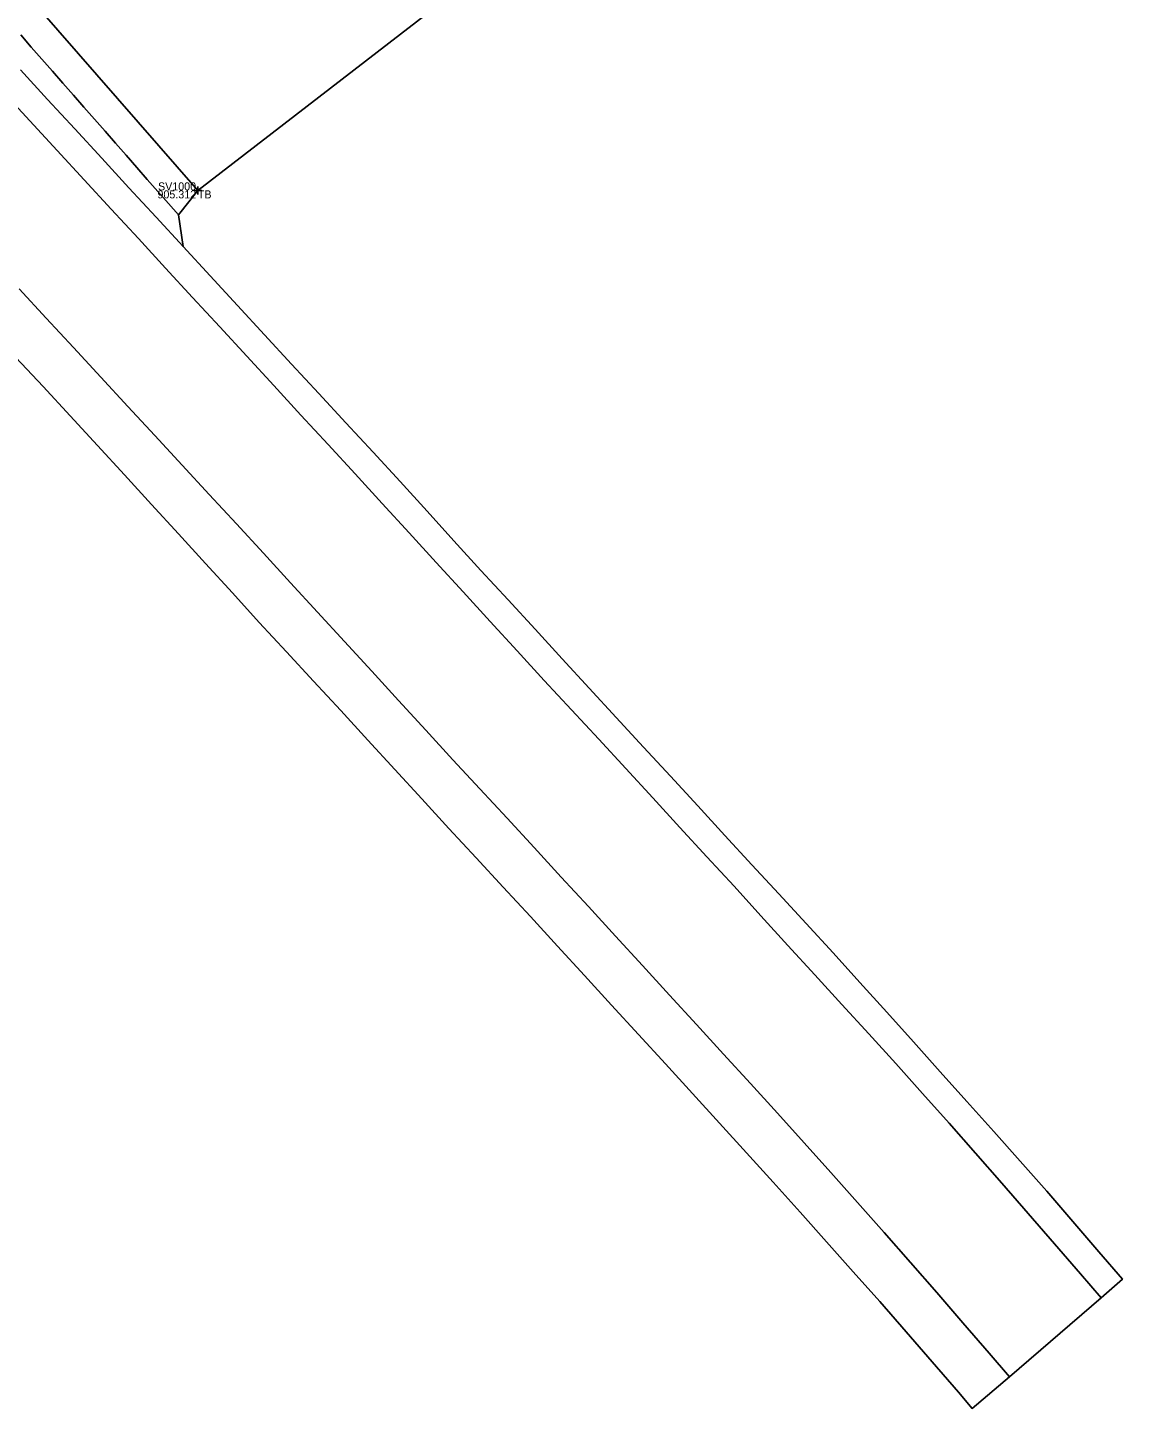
# Model space of a CAD drawing. Extents: x 1918148 to 1919797, y 624701 to 627089.
# Drawn here: x 1919158.7 to 1919295.6, y 625225.5 to 625398.1 of the extents above; entities that cross this region are included whole.
import ezdxf

# ---------------------------------------------------------------- set-up
doc = ezdxf.new("R2010")
doc.units = 0
for name, color, linetype in [('DT_X_Terrain_Boundary', 7, 'Continuous'), ('PM_X_Edge_Line', 7, 'Continuous'), ('PV_X_Shoulder_Aggregate', 7, 'Continuous'), ('RD_X_Concrete_Pad', 7, 'Continuous'), ('SV_X_Shot_Marker', 7, 'Continuous'), ('SV_X_Text_Comment', 7, 'Continuous'), ('SV_X_Text_Elevation', 7, 'Continuous'), ('SV_X_Text_Name', 7, 'Continuous'), ('SV_X_Top_of_Bank', 7, 'Continuous')]:
    doc.layers.add(name, color=color, linetype=linetype)

msp = doc.modelspace()

# ---------------------------------------------------------------- linework, layer by layer
at = {"layer": 'DT_X_Terrain_Boundary'}
msp.add_lwpolyline([(1919157.27, 625356.9), (1919160.68, 625353.24), (1919164.08, 625349.57), (1919167.47, 625345.9), (1919170.85, 625342.21), (1919174.22, 625338.52), (1919177.59, 625334.83), (1919180.97, 625331.14), (1919184.34, 625327.45), (1919187.71, 625323.76), (1919191.11, 625320.09), (1919194.5, 625316.41), (1919197.89, 625312.74), (1919201.27, 625309.06), (1919204.66, 625305.38), (1919208.04, 625301.7), (1919211.42, 625298.01), (1919214.81, 625294.33), (1919218.2, 625290.66), (1919221.6, 625287), (1919224.98, 625283.31), (1919228.35, 625279.62), (1919231.73, 625275.94), (1919235.12, 625272.25), (1919238.49, 625268.57), (1919241.86, 625264.87), (1919245.23, 625261.18), (1919248.6, 625257.48), (1919251.97, 625253.79), (1919255.31, 625250.06), (1919258.64, 625246.34), (1919261.97, 625242.61), (1919265.29, 625238.87), (1919268.58, 625235.11), (1919271.85, 625231.32), (1919275.11, 625227.53), (1919276.83, 625225.52), (1919281.5, 625229.47), (1919292.95, 625239.36), (1919295.61, 625241.67), (1919292.67, 625245.09), (1919289.41, 625248.88), (1919286.15, 625252.67), (1919282.84, 625256.42), (1919279.52, 625260.15), (1919276.18, 625263.88), (1919272.85, 625267.61), (1919269.51, 625271.33), (1919266.15, 625275.03), (1919262.8, 625278.74), (1919259.44, 625282.45), (1919256.08, 625286.15), (1919252.68, 625289.82), (1919249.28, 625293.48), (1919245.89, 625297.15), (1919242.52, 625300.84), (1919239.13, 625304.53), (1919235.73, 625308.19), (1919232.34, 625311.87), (1919228.96, 625315.55), (1919225.57, 625319.23), (1919222.19, 625322.91), (1919218.81, 625326.59), (1919215.42, 625330.27), (1919212.05, 625333.97), (1919208.69, 625337.66), (1919205.32, 625341.36), (1919201.93, 625345.03), (1919198.53, 625348.7), (1919195.14, 625352.38), (1919191.75, 625356.05), (1919188.36, 625359.73), (1919184.97, 625363.4), (1919181.58, 625367.08), (1919178.19, 625370.75), (1919177.59, 625374.71), (1919180.03, 625377.77), (1919214.66, 625404.51)], dxfattribs=at)
at = {"layer": 'PM_X_Edge_Line'}
for points in [[(1919155.66, 625390.14), (1919159.04, 625386.45), (1919162.42, 625382.77), (1919165.81, 625379.09), (1919169.2, 625375.41), (1919172.59, 625371.74), (1919175.98, 625368.06), (1919179.37, 625364.39), (1919182.76, 625360.71), (1919186.14, 625357.03), (1919189.53, 625353.36), (1919192.92, 625349.68), (1919196.31, 625346.01), (1919199.69, 625342.32), (1919203.07, 625338.64), (1919206.45, 625334.95), (1919209.83, 625331.27), (1919213.21, 625327.58), (1919216.58, 625323.89), (1919219.96, 625320.2), (1919223.34, 625316.52), (1919226.74, 625312.85), (1919230.14, 625309.19), (1919233.54, 625305.52), (1919236.92, 625301.84), (1919240.3, 625298.15), (1919243.68, 625294.47), (1919247.06, 625290.78), (1919250.43, 625287.09), (1919253.8, 625283.39), (1919257.17, 625279.7), (1919260.54, 625276.01), (1919263.91, 625272.32), (1919267.29, 625268.63), (1919270.62, 625264.9), (1919273.94, 625261.16), (1919277.25, 625257.42), (1919280.55, 625253.66), (1919283.85, 625249.9), (1919287.12, 625246.11), (1919290.38, 625242.33), (1919292.95, 625239.36)], [(1919157.69, 625365.45), (1919161.08, 625361.78), (1919164.48, 625358.11), (1919167.88, 625354.44), (1919171.27, 625350.77), (1919174.67, 625347.11), (1919178.07, 625343.44), (1919181.46, 625339.77), (1919184.86, 625336.1), (1919188.24, 625332.42), (1919191.62, 625328.73), (1919195, 625325.05), (1919198.38, 625321.36), (1919201.76, 625317.68), (1919205.13, 625313.99), (1919208.51, 625310.3), (1919211.89, 625306.61), (1919215.29, 625302.95), (1919218.69, 625299.28), (1919222.09, 625295.62), (1919225.47, 625291.93), (1919228.85, 625288.25), (1919232.23, 625284.56), (1919235.61, 625280.87), (1919238.98, 625277.18), (1919242.35, 625273.49), (1919245.73, 625269.81), (1919249.11, 625266.12), (1919252.49, 625262.43), (1919255.84, 625258.73), (1919259.17, 625255), (1919262.49, 625251.26), (1919265.81, 625247.52), (1919269.11, 625243.76), (1919272.4, 625240), (1919275.67, 625236.21), (1919278.94, 625232.43), (1919281.5, 625229.47)]]:
    msp.add_lwpolyline(points, dxfattribs=at)
at = {"layer": 'PV_X_Shoulder_Aggregate'}
msp.add_lwpolyline([(1919157.89, 625397.2), (1919159.2, 625395.69), (1919160.52, 625394.19), (1919161.84, 625392.68), (1919163.16, 625391.18), (1919164.48, 625389.68), (1919165.79, 625388.17), (1919167.11, 625386.67), (1919168.43, 625385.16), (1919169.75, 625383.66), (1919171.07, 625382.16), (1919172.38, 625380.65), (1919173.7, 625379.15), (1919175.02, 625377.64), (1919176.34, 625376.14), (1919177.59, 625374.71)], dxfattribs=at)
at = {"layer": 'RD_X_Concrete_Pad'}
for points in [[(1919157.87, 625392.82), (1919161.25, 625389.13), (1919164.63, 625385.45), (1919168.02, 625381.78), (1919171.41, 625378.1), (1919174.8, 625374.43), (1919178.19, 625370.75), (1919181.58, 625367.08), (1919184.97, 625363.4), (1919188.36, 625359.73), (1919191.75, 625356.05), (1919195.14, 625352.38), (1919198.53, 625348.7), (1919201.93, 625345.03), (1919205.32, 625341.36), (1919208.69, 625337.66), (1919212.05, 625333.97), (1919215.42, 625330.27), (1919218.81, 625326.59), (1919222.19, 625322.91), (1919225.57, 625319.23), (1919228.96, 625315.55), (1919232.34, 625311.87), (1919235.73, 625308.19), (1919239.13, 625304.53), (1919242.52, 625300.84), (1919245.89, 625297.15), (1919249.28, 625293.48), (1919252.68, 625289.82), (1919256.08, 625286.15), (1919259.44, 625282.45), (1919262.8, 625278.74), (1919266.15, 625275.03), (1919269.51, 625271.33), (1919272.85, 625267.61), (1919276.18, 625263.88), (1919279.52, 625260.15), (1919282.84, 625256.42), (1919286.15, 625252.67), (1919289.41, 625248.88), (1919292.67, 625245.09), (1919295.61, 625241.67)], [(1919157.27, 625356.9), (1919160.68, 625353.24), (1919164.08, 625349.57), (1919167.47, 625345.9), (1919170.85, 625342.21), (1919174.22, 625338.52), (1919177.59, 625334.83), (1919180.97, 625331.14), (1919184.34, 625327.45), (1919187.71, 625323.76), (1919191.11, 625320.09), (1919194.5, 625316.41), (1919197.89, 625312.74), (1919201.27, 625309.06), (1919204.66, 625305.38), (1919208.04, 625301.7), (1919211.42, 625298.01), (1919214.81, 625294.33), (1919218.2, 625290.66), (1919221.6, 625287), (1919224.98, 625283.31), (1919228.35, 625279.62), (1919231.73, 625275.94), (1919235.12, 625272.25), (1919238.49, 625268.57), (1919241.86, 625264.87), (1919245.23, 625261.18), (1919248.6, 625257.48), (1919251.97, 625253.79), (1919255.31, 625250.06), (1919258.64, 625246.34), (1919261.97, 625242.61), (1919265.29, 625238.87), (1919268.58, 625235.11), (1919271.85, 625231.32), (1919275.11, 625227.53), (1919276.83, 625225.52)]]:
    msp.add_lwpolyline(points, dxfattribs=at)
at = {"layer": 'SV_X_Shot_Marker'}
for p, q in [((1919180.03, 625378.27), (1919180.03, 625377.27)), ((1919179.53, 625377.77), (1919180.53, 625377.77)), ((1919180.03, 625377.77), (1919180.03, 625377.77))]:
    msp.add_line(p, q, dxfattribs=at)
at = {"layer": 'SV_X_Top_of_Bank'}
msp.add_lwpolyline([(1919180.03, 625377.77), (1919142.39, 625420.85), (1919113.9, 625458.17), (1919086.6, 625489.42), (1919057.39, 625523.08), (1919019.76, 625570.22), (1918998.07, 625602.27), (1918985.26, 625627.56), (1918968.39, 625668.03), (1918955.62, 625707.63), (1918947.9, 625739.17), (1918945.04, 625765.59), (1918947.37, 625785.94), (1918957.93, 625802.75), (1918975.61, 625809.21), (1918997.58, 625813.39), (1919030.67, 625814.44), (1919065.45, 625812.35), (1919111.29, 625808.54)], dxfattribs=at)

# ---------------------------------------------------------------- texts
at = {"layer": 'SV_X_Text_Comment'}
msp.add_text('TB', height=1, dxfattribs=at).set_placement((1919180.03, 625376.77))
at = {"layer": 'SV_X_Text_Elevation'}
msp.add_text('905.312', height=1, dxfattribs=at).set_placement((1919174.98, 625376.77))
at = {"layer": 'SV_X_Text_Name'}
msp.add_text('SV1000', height=1, dxfattribs=at).set_placement((1919175.05, 625377.77))

doc.saveas('drawing.dxf')
